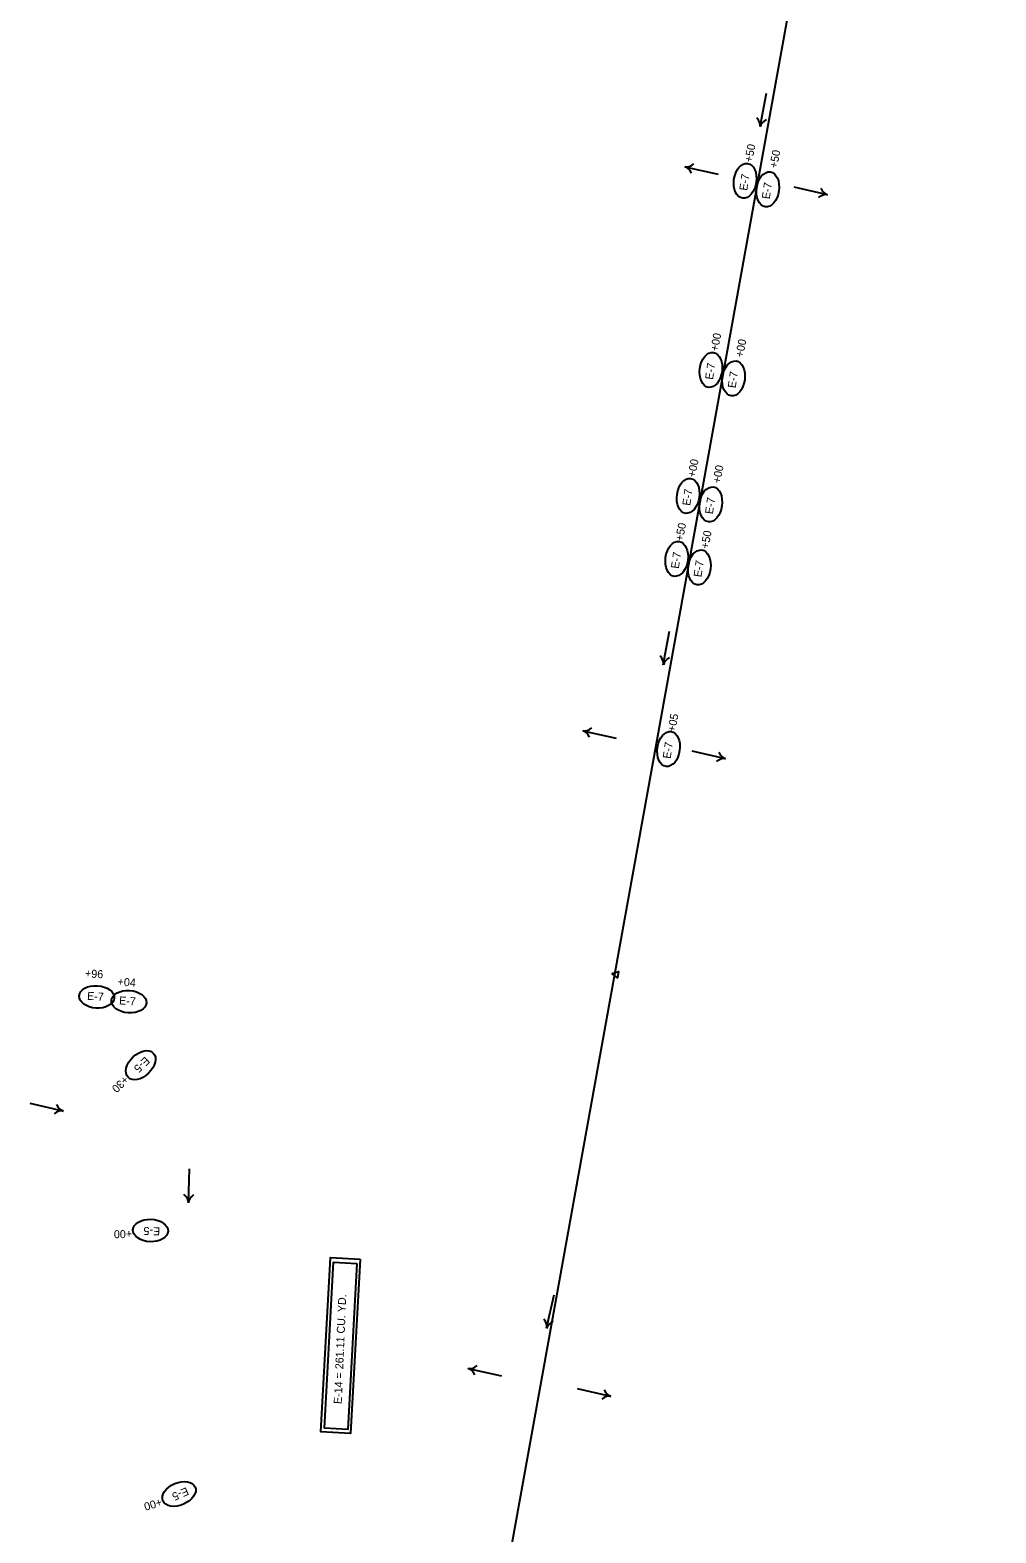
# Model space of a CAD drawing. Extents: x 669236 to 673912, y 735758 to 754788.
# Drawn here: x 670506 to 671260, y 743056 to 744229 of the extents above; entities that cross this region are included whole.
import ezdxf

# ---------------------------------------------------------------- set-up
doc = ezdxf.new("R2010")
doc.units = 0
for name, color, linetype in [('Default', 7, 'Continuous'), ('Prop_Horiz Alignment', 7, 'Continuous'), ('R_Erosion_2', 7, 'Continuous'), ('R_Flow Arrows', 7, 'Continuous')]:
    doc.layers.add(name, color=color, linetype=linetype)

msp = doc.modelspace()

# ---------------------------------------------------------------- linework, layer by layer
at = {"layer": 'Default'}
for p, q in [((670962.6, 743492), (671260.2, 745139.8)), ((670518, 741030.5), (670962.6, 743492))]:
    msp.add_line(p, q, dxfattribs=at)
at = {"layer": 'Prop_Horiz Alignment'}
msp.add_lwpolyline([(670960.1, 743492.4), (670965.5, 743494), (670964.6, 743489.1)], close=True, dxfattribs=at)
at = {"layer": 'R_Erosion_2'}
for points in [[(670763.6, 743269.5), (670756.1, 743133.3), (670733, 743134.6), (670740.5, 743270.8)], [(670761.1, 743266), (670753.9, 743136.4), (670735.7, 743137.4), (670742.9, 743267)]]:
    msp.add_lwpolyline(points, close=True, dxfattribs=at)
for centre, major_axis in [((671064.3, 744111.4), (1.9, 13.6)), ((671082, 744104.8), (1.9, 13.6)), ((671037.6, 743963.8), (1.9, 13.6)), ((671055.3, 743957.2), (1.9, 13.6)), ((671019.8, 743865.4), (1.9, 13.6)), ((671037.5, 743858.8), (1.9, 13.6)), ((671010.9, 743816.2), (1.9, 13.6)), ((671028.6, 743809.6), (1.9, 13.6)), ((671004.5, 743667.8), (1.9, 13.6)), ((670557.9, 743474.2), (13.7, -0.9)), ((670583, 743470.5), (13.7, -0.9)), ((670592.2, 743420.9), (-9.87, -9.49)), ((670599.9, 743291.8), (-13.7, 0.5)), ((670622.2, 743086.1), (-12.6, -5.4))]:
    msp.add_ellipse(centre, major_axis=major_axis, ratio=0.638788, dxfattribs=at)
at = {"layer": 'R_Flow Arrows'}
for p, q in [((671076.1, 744153.8), (671081, 744179.9)), ((671017.3, 744122.3), (671043.2, 744116.6)), ((671128.6, 744100.6), (671102.7, 744106.4)), ((671000.4, 743733.6), (671005.3, 743759.8)), ((670937.6, 743682), (670963.5, 743676.2)), ((671048.9, 743660.2), (671023, 743666)), ((670531.7, 743385.1), (670505.8, 743390.9)), ((670629.5, 743313.5), (670630.3, 743340)), ((670909.3, 743215.5), (670915.1, 743241.5)), ((670848.1, 743184.1), (670874, 743178.3)), ((670959.4, 743162.3), (670933.5, 743168.1))]:
    msp.add_line(p, q, dxfattribs=at)
for centre, major_axis, start_param, end_param in [((671056.2, 744157.2), (19.8, -3.7), 0.023252, 0.620249), ((671095.8, 744149.6), (-19.8, 3.7), 5.662936, 6.259934), ((671012.5, 744102.8), (4.4, 19.7), 5.662936, 6.259934), ((671021.4, 744142.1), (-4.4, -19.7), 0.023252, 0.620249), ((671133.4, 744120.2), (-4.4, -19.7), 5.662936, 6.259934), ((671124.5, 744080.9), (4.4, 19.7), 0.023252, 0.620249), ((670980.6, 743737), (19.8, -3.7), 0.023252, 0.620249), ((671020.2, 743729.5), (-19.8, 3.7), 5.662936, 6.259934), ((670932.8, 743662.4), (4.4, 19.7), 5.662936, 6.259934), ((670941.7, 743701.7), (-4.4, -19.7), 0.023252, 0.620249), ((671044.8, 743640.5), (4.4, 19.7), 0.023252, 0.620249), ((671053.7, 743679.8), (-4.4, -19.7), 5.662936, 6.259934), ((670536.5, 743404.7), (-4.4, -19.7), 5.662936, 6.259934), ((670527.6, 743365.4), (4.4, 19.7), 0.023252, 0.620249), ((670609.4, 743313.8), (20.2, -0.6), 0.023252, 0.620249), ((670649.7, 743312.5), (-20.2, 0.6), 5.662936, 6.259934), ((670889.6, 743219.7), (19.7, -4.4), 0.023252, 0.620249), ((670928.9, 743210.7), (-19.7, 4.4), 5.662936, 6.259934), ((670843.2, 743164.5), (4.4, 19.7), 5.662936, 6.259934), ((670852.2, 743203.8), (-4.4, -19.7), 0.023252, 0.620249), ((670964.2, 743181.9), (-4.4, -19.7), 5.662936, 6.259934), ((670955.3, 743142.6), (4.4, 19.7), 0.023252, 0.620249)]:
    msp.add_ellipse(centre, major_axis=major_axis, ratio=0.5625, start_param=start_param, end_param=end_param, dxfattribs=at)

# ---------------------------------------------------------------- texts
at = {"layer": 'R_Erosion_2'}
for s, rotation, p in [('+50', 79.2728, (671069.8, 744125.6)), ('+50', 79.2728, (671089.3, 744121)), ('E-7', 81.9991, (671065.9, 744103.5)), ('E-7', 81.9991, (671083.5, 744096.9)), ('+00', 79.2728, (671043.1, 743978)), ('+00', 79.2728, (671062.7, 743973.3)), ('E-7', 81.9991, (671039.2, 743955.9)), ('E-7', 81.9991, (671056.9, 743949.3)), ('+00', 79.2728, (671025.4, 743879.6)), ('+00', 79.2728, (671044.9, 743874.9)), ('E-7', 81.9991, (671021.4, 743857.5)), ('E-7', 81.9991, (671039.1, 743850.9)), ('+50', 79.2728, (671015.7, 743829.8)), ('+50', 79.2728, (671035.6, 743823.8)), ('E-7', 81.9991, (671012.5, 743808.3)), ('E-7', 81.9991, (671030.2, 743801.7)), ('+05', 79.2728, (671009.7, 743680.8)), ('E-7', 81.9991, (671006.1, 743659.9)), ('+96', 356.9939, (670548.6, 743489.5)), ('+04', 356.9939, (670574.1, 743483)), ('E-7', 356.2996, (670550.2, 743472)), ('E-7', 356.2996, (670575.2, 743468.4)), ('E-5', 223.8811, (670595.7, 743428)), ('+30', 224.0467, (670579.3, 743413.2)), ('E-5', 177.9137, (670607.5, 743294.2)), ('+00', 180.7555, (670585.4, 743292.2)), ('E-14 = 261.11 CU. YD.', 87.5732, (670749.2, 743156.2)), ('E-5', 203.2737, (670628, 743091.5)), ('+00', 196.442, (670607.8, 743082.9))]:
    msp.add_text(s, height=6.25, rotation=rotation, dxfattribs=at).set_placement(p)

doc.saveas('drawing.dxf')
